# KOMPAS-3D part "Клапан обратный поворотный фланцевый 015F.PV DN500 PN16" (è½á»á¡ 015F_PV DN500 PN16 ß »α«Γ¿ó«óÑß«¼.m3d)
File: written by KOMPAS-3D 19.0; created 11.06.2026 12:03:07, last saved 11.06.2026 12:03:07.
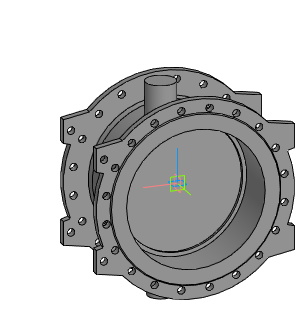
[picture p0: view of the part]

Document properties: Автор: Энергия; Полное имя файла: Z:\3.Личные\kachalov\001_3d для проектировщиков\5.5 Тип 015F.PV Клапан обратный поворотный с двумя эксцентриками\_stp_Клапан 015F.PV DN300-DN1200 с противовесом\Клапан 015F_PV DN500 PN16 с противовесом.m3d

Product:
- Part/product: Клапан обратный поворотный фланцевый 015F.PV DN500 PN16

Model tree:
1. Операция без истории:1
2. Сплайн:1
     Координата Y = 30; Координата Z = 250; Вес = 1; Координата X = 500; Координата Y = 95.8262; Координата Z = 250; Вес = 0.333333; Координата X = 500; Координата Y = 95.8262; Координата Z = -250; Вес = 0.333333; Координата Y = 30; Координата Z = -250; Вес = 1; Координата X = -500; Координата Y = -35.8262; Координата Z = -250; Вес = 0.333333; Координата X = -500; Координата Y = -35.8262; Координата Z = 250; Вес = 0.333333; Порядок = 4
